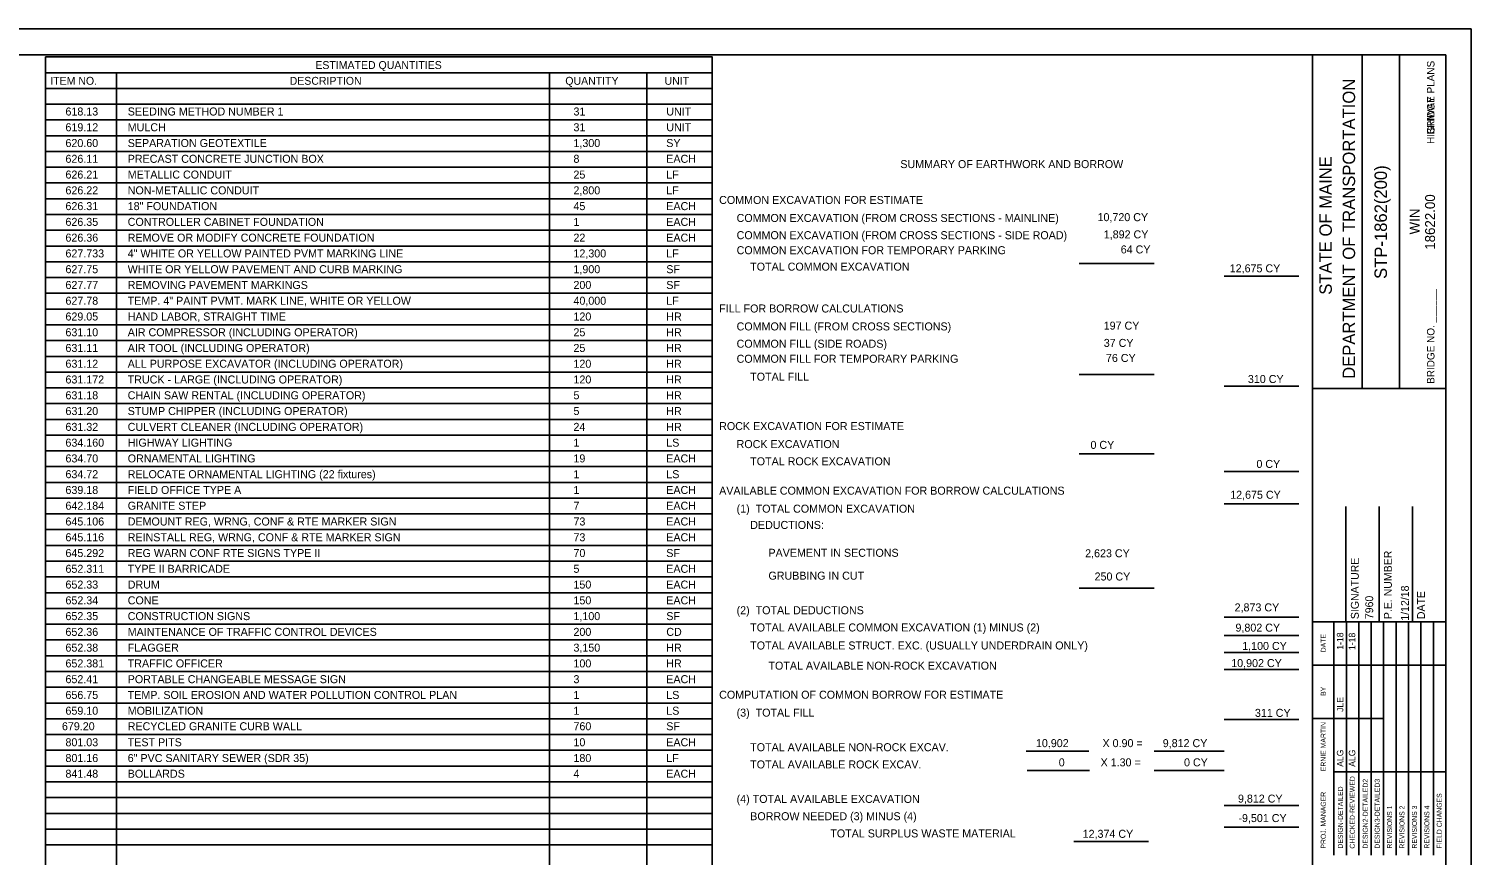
# Model space of a CAD drawing. Extents: x -0.13 to 2.7, y -0.05 to 1.78.
# Drawn here: x 0.896 to 2.698, y 0.75 to 1.782 of the extents above; entities that cross this region are included whole.
import ezdxf

# ---------------------------------------------------------------- set-up
doc = ezdxf.new("R2010")
doc.units = 0
for name, color, linetype in [('ANNOTATION', 7, 'Continuous'), ('BORDER', 7, 'Continuous'), ('BRIDGE_TITLE', 7, 'Continuous'), ('Default', 7, 'Continuous'), ('HIGHWAY_TITLE', 7, 'Continuous'), ('PLOT BOUNDARY', 7, 'Continuous')]:
    doc.layers.add(name, color=color, linetype=linetype)

msp = doc.modelspace()

# ---------------------------------------------------------------- linework, layer by layer
at = {"layer": 'BORDER'}
for p, q in [((2.6667, 1.75), (0, 1.75)), ((2.5, 0), (2.5, 1.75)), ((2.5621, 1.3333), (2.5621, 1.75)), ((2.6087, 1.3333), (2.6087, 1.75)), ((2.6667, 0), (2.6667, 1.75)), ((0.9167, 1.7276), (1.75, 1.7276)), ((1.0052, 1.7276), (1.0052, 0.0149)), ((1.5466, 1.7276), (1.5466, 0.0149)), ((1.668, 1.7276), (1.668, 0.0149)), ((0.9167, 1.7079), (1.75, 1.7079)), ((0.9167, 1.6882), (1.75, 1.6882)), ((0.9167, 1.6685), (1.75, 1.6685)), ((0.9167, 1.6488), (1.75, 1.6488)), ((0.9167, 1.6292), (1.75, 1.6292)), ((0.9167, 1.6095), (1.75, 1.6095)), ((0.9167, 1.5898), (1.75, 1.5898)), ((0.9167, 1.5701), (1.75, 1.5701)), ((0.9167, 1.5504), (1.75, 1.5504)), ((0.9167, 1.5307), (1.75, 1.5307)), ((0.9167, 1.511), (1.75, 1.511)), ((0.9167, 1.4914), (1.75, 1.4914)), ((0.9167, 1.4717), (1.75, 1.4717)), ((0.9167, 1.452), (1.75, 1.452)), ((0.9167, 1.4323), (1.75, 1.4323)), ((0.9167, 1.4126), (1.75, 1.4126)), ((0.9167, 1.3929), (1.75, 1.3929)), ((0.9167, 1.3732), (1.75, 1.3732)), ((0.9167, 1.3536), (1.75, 1.3536)), ((0.9167, 1.3339), (1.75, 1.3339)), ((2.5, 1.3332), (2.6667, 1.3332)), ((0.9167, 1.3142), (1.75, 1.3142)), ((0.9167, 1.2945), (1.75, 1.2945)), ((0.9167, 1.2748), (1.75, 1.2748)), ((0.9167, 1.2551), (1.75, 1.2551)), ((0.9167, 1.2354), (1.75, 1.2354)), ((0.9167, 1.2158), (1.75, 1.2158)), ((0.9167, 1.1961), (1.75, 1.1961)), ((0.9167, 1.1764), (1.75, 1.1764)), ((2.5417, 1.0417), (2.5417, 1.1858)), ((2.5833, 1.0417), (2.5833, 1.1858)), ((2.625, 1.0417), (2.625, 1.1858)), ((0.9167, 1.1567), (1.75, 1.1567)), ((0.9167, 1.137), (1.75, 1.137)), ((0.9167, 1.1173), (1.75, 1.1173)), ((0.9167, 1.0976), (1.75, 1.0976)), ((0.9167, 1.0779), (1.75, 1.0779)), ((0.9167, 1.0583), (1.75, 1.0583)), ((0.9167, 1.0386), (1.75, 1.0386)), ((2.5, 1.0417), (2.6667, 1.0417)), ((0.9167, 1.0189), (1.75, 1.0189)), ((0.9167, 0.9992), (1.75, 0.9992)), ((0.9167, 0.9795), (1.75, 0.9795)), ((0.9167, 0.9598), (1.75, 0.9598)), ((0.9167, 0.9401), (1.75, 0.9401)), ((0.9167, 0.9205), (1.75, 0.9205)), ((0.9167, 0.9008), (1.75, 0.9008)), ((0.9167, 0.8811), (1.75, 0.8811)), ((0.9167, 0.8614), (1.75, 0.8614)), ((0.9167, 0.8417), (1.75, 0.8417)), ((0.9167, 0.822), (1.75, 0.822)), ((0.9167, 0.8023), (1.75, 0.8023)), ((0.9167, 0.7827), (1.75, 0.7827)), ((0.9167, 0.763), (1.75, 0.763))]:
    msp.add_line(p, q, dxfattribs=at)
msp.add_lwpolyline([(0.9167, 1.7473), (1.75, 1.7473), (1.75, 0.0149), (0.9167, 0.0149)], close=True, dxfattribs=at)
for points in [[(2.5269, 0.9875), (2.5269, 1.0417)], [(2.5269, 0.7501), (2.5269, 1.0299)], [(2.5425, 0.7501), (2.5425, 1.0417)], [(2.558, 1.0417), (2.558, 0.7501)], [(2.5735, 0.7501), (2.5735, 1.0417)], [(2.589, 0.7501), (2.589, 1.0417)], [(2.6046, 0.7501), (2.6046, 1.0417)], [(2.6201, 0.7501), (2.6201, 1.0417)], [(2.6356, 0.7501), (2.6356, 1.0417)], [(2.6512, 0.7501), (2.6512, 1.0417)], [(2.5, 0.9875), (2.6667, 0.9875)], [(2.5, 0.9209), (2.5269, 0.9209)], [(2.5269, 0.9209), (2.589, 0.9209)], [(2.5269, 0.8542), (2.6667, 0.8542)]]:
    msp.add_lwpolyline(points, dxfattribs=at)
at = {"layer": 'Default'}
for p, q in [((2.2087, 1.4892), (2.3022, 1.4892)), ((2.3897, 1.4734), (2.4831, 1.4734)), ((2.2087, 1.3506), (2.3022, 1.3506)), ((2.3897, 1.3358), (2.4831, 1.3358)), ((2.2087, 1.2514), (2.3022, 1.2514)), ((2.3897, 1.2292), (2.4831, 1.2292)), ((2.3897, 1.189), (2.4831, 1.189)), ((2.2087, 1.0835), (2.3022, 1.0835)), ((2.3897, 1.0474), (2.4831, 1.0474)), ((2.3897, 1.0243), (2.4831, 1.0243)), ((2.3897, 1.0031), (2.4831, 1.0031)), ((2.3897, 0.9818), (2.4831, 0.9818)), ((2.3897, 0.9196), (2.4831, 0.9196)), ((2.1425, 0.8798), (2.2205, 0.8798)), ((2.3022, 0.8798), (2.3897, 0.8798)), ((2.1436, 0.8559), (2.2216, 0.8559)), ((2.3022, 0.8559), (2.3897, 0.8559)), ((2.3897, 0.812), (2.4831, 0.812)), ((2.3897, 0.785), (2.4831, 0.785)), ((2.2017, 0.7671), (2.2951, 0.7671))]:
    msp.add_line(p, q, dxfattribs=at)
at = {"layer": 'PLOT BOUNDARY'}
msp.add_lwpolyline([(-0.1349, -0.051), (2.6984, -0.051), (2.6984, 1.7823), (-0.1349, 1.7823)], close=True, dxfattribs=at)

# ---------------------------------------------------------------- texts
at = {"layer": 'ANNOTATION'}
for s, p in [('618.13', (0.9416, 1.6741)), ('SEEDING METHOD NUMBER 1', (1.0194, 1.6741)), ('31', (1.5765, 1.6741)), ('UNIT', (1.6925, 1.6741)), ('619.12', (0.9416, 1.6544)), ('MULCH', (1.0194, 1.6544)), ('31', (1.5765, 1.6544)), ('UNIT', (1.6925, 1.6544)), ('620.60', (0.9416, 1.6347)), ('SEPARATION GEOTEXTILE', (1.0194, 1.6347)), ('1,300', (1.5765, 1.6347)), ('SY', (1.6925, 1.6347)), ('626.11', (0.9416, 1.615)), ('PRECAST CONCRETE JUNCTION BOX', (1.0194, 1.615)), ('8', (1.5765, 1.615)), ('EACH', (1.6925, 1.615)), ('626.21', (0.9416, 1.5953)), ('METALLIC CONDUIT', (1.0194, 1.5953)), ('25', (1.5765, 1.5953)), ('LF', (1.6925, 1.5953)), ('626.22', (0.9416, 1.5756)), ('NON-METALLIC CONDUIT', (1.0194, 1.5756)), ('2,800', (1.5765, 1.5756)), ('LF', (1.6925, 1.5756)), ('626.31', (0.9416, 1.5559)), ('18" FOUNDATION', (1.0194, 1.5559)), ('45', (1.5765, 1.5559)), ('EACH', (1.6925, 1.5559)), ('626.35', (0.9416, 1.5362)), ('CONTROLLER CABINET FOUNDATION', (1.0194, 1.5362)), ('1', (1.5765, 1.5362)), ('EACH', (1.6925, 1.5362)), ('626.36', (0.9416, 1.5165)), ('REMOVE OR MODIFY CONCRETE FOUNDATION', (1.0194, 1.5165)), ('22', (1.5765, 1.5165)), ('EACH', (1.6925, 1.5165)), ('627.733', (0.9416, 1.4968)), ('4" WHITE OR YELLOW PAINTED PVMT MARKING LINE ', (1.0194, 1.4968)), ('12,300', (1.5765, 1.4968)), ('LF', (1.6925, 1.4968)), ('627.75', (0.9416, 1.4771)), ('WHITE OR YELLOW PAVEMENT AND CURB MARKING', (1.0194, 1.4771)), ('1,900', (1.5765, 1.4771)), ('SF', (1.6925, 1.4771)), ('627.77', (0.9416, 1.4574)), ('REMOVING PAVEMENT MARKINGS', (1.0194, 1.4574)), ('200', (1.5765, 1.4574)), ('SF', (1.6925, 1.4574)), ('627.78', (0.9416, 1.4377)), ('TEMP. 4" PAINT PVMT. MARK LINE, WHITE OR YELLOW', (1.0194, 1.4377)), ('40,000', (1.5765, 1.4377)), ('LF', (1.6925, 1.4377)), ('629.05', (0.9416, 1.418)), ('HAND LABOR, STRAIGHT TIME', (1.0194, 1.418)), ('120', (1.5765, 1.418)), ('HR', (1.6925, 1.418)), ('631.10', (0.9416, 1.3983)), ('AIR COMPRESSOR (INCLUDING OPERATOR)', (1.0194, 1.3983)), ('25', (1.5765, 1.3983)), ('HR', (1.6925, 1.3983)), ('631.11', (0.9416, 1.3787)), ('AIR TOOL (INCLUDING OPERATOR)', (1.0194, 1.3787)), ('25', (1.5765, 1.3787)), ('HR', (1.6925, 1.3787)), ('631.12', (0.9416, 1.359)), ('ALL PURPOSE EXCAVATOR (INCLUDING OPERATOR)', (1.0194, 1.359)), ('120', (1.5765, 1.359)), ('HR', (1.6925, 1.359)), ('631.172', (0.9416, 1.3393)), ('TRUCK - LARGE (INCLUDING OPERATOR)', (1.0194, 1.3393)), ('120', (1.5765, 1.3393)), ('HR', (1.6925, 1.3393)), ('631.18', (0.9416, 1.3196)), ('CHAIN SAW RENTAL (INCLUDING OPERATOR)', (1.0194, 1.3196)), ('5', (1.5765, 1.3196)), ('HR', (1.6925, 1.3196)), ('631.20', (0.9416, 1.2999)), ('STUMP CHIPPER (INCLUDING OPERATOR)', (1.0194, 1.2999)), ('5', (1.5765, 1.2999)), ('HR', (1.6925, 1.2999)), ('631.32', (0.9416, 1.2801)), ('CULVERT CLEANER (INCLUDING OPERATOR)', (1.0194, 1.2801)), ('24', (1.5765, 1.2801)), ('HR', (1.6925, 1.2801)), ('634.160', (0.9416, 1.2604)), ('HIGHWAY LIGHTING', (1.0194, 1.2604)), ('1', (1.5765, 1.2604)), ('LS', (1.6925, 1.2604)), ('634.70', (0.9416, 1.2407)), ('ORNAMENTAL LIGHTING', (1.0194, 1.2407)), ('19', (1.5765, 1.2407)), ('EACH', (1.6925, 1.2407)), ('634.72', (0.9416, 1.221)), ('RELOCATE ORNAMENTAL LIGHTING (22 fixtures)', (1.0194, 1.221)), ('1', (1.5765, 1.221)), ('LS', (1.6925, 1.221)), ('639.18', (0.9416, 1.2013)), ('FIELD OFFICE TYPE A', (1.0194, 1.2013)), ('1', (1.5765, 1.2013)), ('EACH', (1.6925, 1.2013)), ('642.184', (0.9416, 1.1816)), ('GRANITE STEP', (1.0194, 1.1816)), ('7', (1.5765, 1.1816)), ('EACH', (1.6925, 1.1816)), ('645.106', (0.9416, 1.1619)), ('DEMOUNT REG, WRNG, CONF & RTE MARKER SIGN', (1.0194, 1.1619)), ('73', (1.5765, 1.1619)), ('EACH', (1.6925, 1.1619)), ('645.116', (0.9416, 1.1422)), ('REINSTALL REG, WRNG, CONF & RTE MARKER SIGN', (1.0194, 1.1422)), ('73', (1.5765, 1.1422)), ('EACH', (1.6925, 1.1422)), ('645.292', (0.9416, 1.1225)), ('REG WARN CONF RTE SIGNS TYPE II', (1.0194, 1.1225)), ('70', (1.5765, 1.1225)), ('SF', (1.6925, 1.1225)), ('652.311', (0.9416, 1.1028)), ('TYPE II BARRICADE', (1.0194, 1.1028)), ('5', (1.5765, 1.1028)), ('EACH', (1.6925, 1.1028)), ('652.33', (0.9416, 1.0831)), ('DRUM', (1.0194, 1.0831)), ('150', (1.5765, 1.0831)), ('EACH', (1.6925, 1.0831)), ('652.34', (0.9416, 1.0634)), ('CONE', (1.0194, 1.0634)), ('150', (1.5765, 1.0634)), ('EACH', (1.6925, 1.0634)), ('652.35', (0.9416, 1.0437)), ('CONSTRUCTION SIGNS', (1.0194, 1.0437)), ('1,100', (1.5765, 1.0437)), ('SF', (1.6925, 1.0437)), ('652.36', (0.9416, 1.024)), ('MAINTENANCE OF TRAFFIC CONTROL DEVICES', (1.0194, 1.024)), ('200', (1.5765, 1.024)), ('CD', (1.6925, 1.024)), ('652.38', (0.9416, 1.0043)), ('FLAGGER', (1.0194, 1.0043)), ('3,150', (1.5765, 1.0043)), ('HR', (1.6925, 1.0043)), ('TOTAL AVAILABLE STRUCT. EXC. (USUALLY UNDERDRAIN ONLY)', (1.7974, 1.007)), ('652.381', (0.9416, 0.9846)), ('TRAFFIC OFFICER', (1.0194, 0.9846)), ('100', (1.5765, 0.9846)), ('HR', (1.6925, 0.9846)), ('652.41', (0.9416, 0.9649)), ('PORTABLE CHANGEABLE MESSAGE SIGN', (1.0194, 0.9649)), ('3', (1.5765, 0.9649)), ('EACH', (1.6925, 0.9649)), ('656.75', (0.9416, 0.9452)), ('TEMP. SOIL EROSION AND WATER POLLUTION CONTROL PLAN', (1.0194, 0.9452)), ('1', (1.5765, 0.9452)), ('LS', (1.6925, 0.9452)), ('659.10', (0.9416, 0.9255)), ('MOBILIZATION', (1.0194, 0.9255)), ('1', (1.5765, 0.9255)), ('LS', (1.6925, 0.9255)), ('679.20', (0.9372, 0.9061)), ('RECYCLED GRANITE CURB WALL', (1.0194, 0.9061)), ('760', (1.5765, 0.9061)), ('SF', (1.6925, 0.9061)), ('801.03', (0.9416, 0.8861)), ('TEST PITS', (1.0194, 0.8861)), ('10', (1.5765, 0.8861)), ('EACH', (1.6925, 0.8861)), ('801.16', (0.9416, 0.8664)), ('6" PVC SANITARY SEWER (SDR 35)', (1.0194, 0.8664)), ('180', (1.5765, 0.8664)), ('LF', (1.6925, 0.8664)), ('841.48', (0.9416, 0.8468)), ('BOLLARDS', (1.0194, 0.8468)), ('4', (1.5765, 0.8468)), ('EACH', (1.6925, 0.8468))]:
    msp.add_text(s, height=0.01, dxfattribs=at).set_placement(p)
at = {"layer": 'BORDER'}
for s, height, p in [('ESTIMATED QUANTITIES', 0.009843, (1.2539, 1.7322)), ('ITEM NO.', 0.00984, (0.9226, 1.7125)), ('DESCRIPTION', 0.009843, (1.2218, 1.7125)), ('QUANTITY', 0.00984, (1.5663, 1.7125)), ('UNIT', 0.00984, (1.6903, 1.7125))]:
    msp.add_text(s, height=height, dxfattribs=at).set_placement(p)
for s, height, p in [('DEPARTMENT OF TRANSPORTATION', 0.015529, (2.5534, 1.3451)), ('STATE OF MAINE', 0.015529, (2.5243, 1.4502)), ('STP-1862(200)', 0.015529, (2.5932, 1.4699)), ('18622.00', 0.01242, (2.6533, 1.5064)), ('WIN', 0.01242, (2.6339, 1.5255)), ('SIGNATURE', 0.00984, (2.558, 1.0449)), ('P.E. NUMBER', 0.009843, (2.5993, 1.0449)), ('1/12/18', 0.00984, (2.6206, 1.043)), ('7960', 0.00984, (2.576, 1.0449)), ('DATE', 0.00984, (2.6407, 1.0449)), ('1-18', 0.00808, (2.5387, 1.0067)), ('DATE', 0.00619, (2.5167, 1.0035)), ('1-18', 0.00808, (2.5536, 1.0063)), ('BY', 0.00619, (2.5167, 0.949)), ('JLE', 0.00808, (2.5387, 0.929)), ('ERNIE MARTIN', 0.006212, (2.5167, 0.8549)), ('ALG', 0.00808, (2.5387, 0.8604)), ('ALG', 0.00808, (2.5536, 0.8604)), ('DESIGN-DETAILED', 0.006212, (2.5381, 0.7582)), ('CHECKED-REVIEWED', 0.006212, (2.553, 0.7582)), ('DESIGN2-DETAILED2', 0.006212, (2.5692, 0.7582)), ('DESIGN3-DETAILED3', 0.006212, (2.5841, 0.7582)), ('PROJ. MANAGER', 0.006212, (2.5167, 0.7582)), ('FIELD CHANGES', 0.006212, (2.6617, 0.7582)), ('REVISIONS 1', 0.006212, (2.5996, 0.7582)), ('REVISIONS 2', 0.006212, (2.6151, 0.7582)), ('REVISIONS 3', 0.006212, (2.6307, 0.7582)), ('REVISIONS 4', 0.006212, (2.6462, 0.7582))]:
    msp.add_text(s, height=height, rotation=90, dxfattribs=at).set_placement(p)
at = {"layer": 'BRIDGE_TITLE'}
for s, p in [('BRIDGE PLANS', (2.6526, 1.6504)), ('BRIDGE NO. ______', (2.6526, 1.3388))]:
    msp.add_text(s, height=0.009317, rotation=90, dxfattribs=at).set_placement(p)
at = {"layer": 'Default'}
for s, p in [('SUMMARY OF EARTHWORK AND BORROW', (1.985, 1.6084)), ('COMMON EXCAVATION FOR ESTIMATE', (1.7586, 1.5636)), ('COMMON EXCAVATION (FROM CROSS SECTIONS - MAINLINE) ', (1.7804, 1.5411)), ('10,720 CY', (2.2315, 1.5421)), ('COMMON EXCAVATION (FROM CROSS SECTIONS - SIDE ROAD) ', (1.7804, 1.5196)), ('1,892 CY', (2.2393, 1.5206)), ('COMMON EXCAVATION FOR TEMPORARY PARKING', (1.7804, 1.5008)), ('64 CY', (2.2605, 1.5018)), ('TOTAL COMMON EXCAVATION', (1.7974, 1.4803)), ('12,675 CY', (2.3967, 1.4782)), ('FILL FOR BORROW CALCULATIONS', (1.7586, 1.428)), ('COMMON FILL (FROM CROSS SECTIONS)', (1.7804, 1.4056)), ('197 CY', (2.2392, 1.4066)), ('COMMON FILL (SIDE ROADS)', (1.7804, 1.384)), ('37 CY', (2.2393, 1.385)), ('COMMON FILL FOR TEMPORARY PARKING', (1.7804, 1.3652)), ('76 CY', (2.242, 1.3662)), ('TOTAL FILL', (1.7974, 1.3428)), ('310 CY', (2.4194, 1.3399)), ('ROCK EXCAVATION FOR ESTIMATE', (1.7586, 1.2811)), ('ROCK EXCAVATION', (1.7804, 1.2586)), ('0 CY', (2.2227, 1.2576)), ('TOTAL ROCK EXCAVATION', (1.7974, 1.2371)), ('0 CY', (2.4301, 1.2338)), ('AVAILABLE COMMON EXCAVATION FOR BORROW CALCULATIONS', (1.7586, 1.2004)), ('12,675 CY', (2.3973, 1.1953)), ('(1)  TOTAL COMMON EXCAVATION', (1.7804, 1.1779)), ('DEDUCTIONS:', (1.7974, 1.1576)), ('PAVEMENT IN SECTIONS', (1.8202, 1.1228)), ('2,623 CY', (2.216, 1.1222)), ('GRUBBING IN CUT', (1.8202, 1.0942)), ('250 CY', (2.2278, 1.0932)), ('2,873 CY', (2.4028, 1.0546)), ('(2)  TOTAL DEDUCTIONS', (1.7804, 1.051)), ('TOTAL AVAILABLE COMMON EXCAVATION (1) MINUS (2)', (1.7974, 1.0295)), ('9,802 CY', (2.4039, 1.0293)), ('1,100 CY', (2.4123, 1.0064)), ('TOTAL AVAILABLE NON-ROCK EXCAVATION', (1.8202, 0.9818)), ('10,902 CY', (2.3986, 0.985)), ('COMPUTATION OF COMMON BORROW FOR ESTIMATE', (1.7586, 0.9455)), ('(3)  TOTAL FILL', (1.7804, 0.9231)), ('311 CY', (2.4282, 0.9228)), ('TOTAL AVAILABLE NON-ROCK EXCAV.', (1.7974, 0.8799)), ('10,902', (2.1545, 0.885)), ('X 0.90 =', (2.2377, 0.885)), ('9,812 CY', (2.313, 0.885)), ('TOTAL AVAILABLE ROCK EXCAV.', (1.7974, 0.8584)), ('0', (2.183, 0.861)), ('X 1.30 =', (2.2353, 0.861)), ('0 CY', (2.3396, 0.861)), ('(4) TOTAL AVAILABLE EXCAVATION', (1.7804, 0.8153)), ('9,812 CY', (2.407, 0.8157)), ('BORROW NEEDED (3) MINUS (4)', (1.7974, 0.7937)), ('-9,501 CY', (2.4076, 0.7914)), ('TOTAL SURPLUS WASTE MATERIAL', (1.8975, 0.7722)), ('12,374 CY', (2.2129, 0.7717))]:
    msp.add_text(s, height=0.01, dxfattribs=at).set_placement(p)
at = {"layer": 'HIGHWAY_TITLE'}
msp.add_text('HIGHWAY PLANS', height=0.009317, rotation=90, dxfattribs=at).set_placement((2.6526, 1.6386))

doc.saveas('drawing.dxf')
